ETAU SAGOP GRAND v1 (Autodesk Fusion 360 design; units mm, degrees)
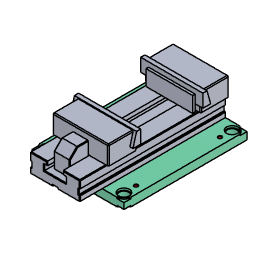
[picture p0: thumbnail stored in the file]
base_feature "Base Feature1"
base_feature "Base Feature1"
as_built_joint "As-built1"
as_built_joint "As-built2"
base_feature "Base Feature1"
as_built_joint "As-built1"
work_plane "WorkPlane1" User Parameter 200 named "Ouverture" User Parameter 8 named "epaisseurcale" User Parameter 50 named "hauteurcale"
sketch "Sketch1" plane through (0, -141, 48) normal (1, 0, 0) x axis (0, 1, 0)
  line L1 (141, 63) -> (133, 63)
  line L2 (141, 13) -> (141, 63)
  line L3 (133, 13) -> (141, 13)
  line L4 (133, 63) -> (133, 13)
  line L5 (-233, 13) -> (233, 13)
  line L6 (141, 78) -> (141, 36)
  point P2 (133, 63)
  point P3 (141, 63)
  point P5 (133, 13)
  horizontal L1
  vertical L2
  horizontal L3
  vertical L4
  collinear L3 L5
  collinear L2 L6
  dimension "d4" distance P2 P3 = 8 (= "epaisseurcale")
  dimension "d5" distance P2 P5 = 50 (= "hauteurcale")
extrude "Extrude1" add sketch "Sketch1" profile of L1 L2 L3 L4 distance 150
sketch "Sketch1" plane through (0, -141, 48) normal (1, 0, 0) x axis (0, 1, 0)
  line L1 (49, 63) -> (41, 63)
  line L2 (49, 13) -> (49, 63)
  line L3 (41, 13) -> (49, 13)
  line L4 (41, 63) -> (41, 13)
  line L5 (41, 36) -> (41, 78)
  line L6 (-233, 13) -> (147, 13)
  point P2 (41, 63)
  point P3 (49, 63)
  point P4 (49, 13)
  horizontal L1
  vertical L2
  horizontal L3
  vertical L4
  collinear L4 L5
  collinear L3 L6
  dimension "d8" distance P2 P3 = 8 (= "epaisseurcale")
  dimension "d9" distance P3 P4 = 50 (= "hauteurcale")
extrude "Extrude1" new body sketch "Sketch1" profile of L1 L2 L3 L4 distance 150
as_built_joint "As-built3"
ground "Ground1"
as_built_joint "As-built2"
joint "Assemble1" alignOffsetX 0 alignOffsetY 0 alignOffsetZ 200 (= "Ouverture")
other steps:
create_component "CreateComponent1"
create_component "CreateComponent1"
create_component "CreateComponent2"
create_component "CreateComponent2"
create_component "CreateComponent1"
joint_origin "JointOrigin1" OffsetX 0 OffsetY 0 OffsetZ 0
joint_origin "JointOrigin1" OffsetX 0 OffsetY 0 OffsetZ 0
